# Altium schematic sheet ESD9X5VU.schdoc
size 127 x 101 mm
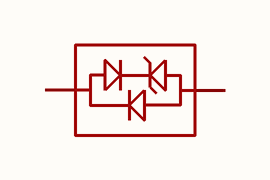
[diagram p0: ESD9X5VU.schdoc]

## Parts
D?  esd9x5vu  [X1-DFN1006-2_L1.0-W0.6-RD]  (value not drawn)

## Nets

Not connected (* = marked no-connect by the designer): D? 1 2

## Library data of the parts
D? = esd9x5vu: 极性:单向;反向截止电压(Vrwm):5V;钳位电压:10V；13V;峰值脉冲电流(Ipp):4A@8/20us;峰值脉冲功率(Ppp):70W@8/20us;击穿电压:7.5V;; Manufacturer: TECH PUBLIC(台舟); AddInBom: yes; ModelId: 286906a806674e89bc4656cc8fde7c56; ModelName: DFN1006_L1.0-W0.6-H0.5; ModelTransform: 40.1574,24.4094,0,0,0,0,0,0,0; Polarity: 单向; Reverse Stand-Off Voltage (Vrwm): 5V; Voltage - Breakdown: 7.5V; Reverse Leakage Current (Ir): 80nA; Number of Channels: 单路; level of protection: IEC 61000-4-2；IEC 61000-4-5; Type: ESD; Junction Capacitance: 0.5pF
